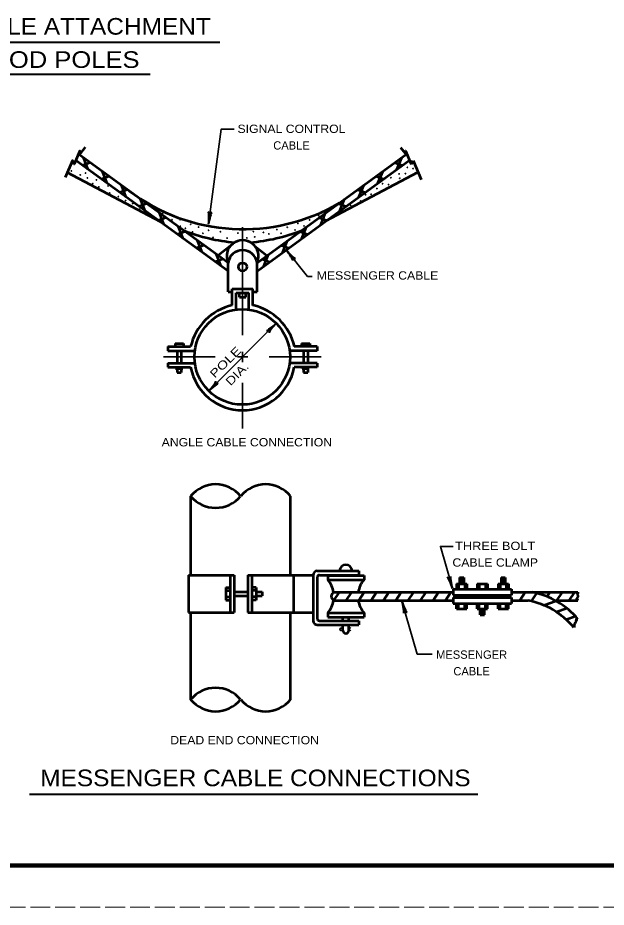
# Model space of a CAD drawing. Extents: x -368 to 312, y -34 to 406.
# Drawn here: x -79.7 to 62, y -34 to 180.1 of the extents above; entities that cross this region are included whole.
import ezdxf
from ezdxf.enums import TextEntityAlignment as Align

# ---------------------------------------------------------------- set-up
doc = ezdxf.new("R2010")
doc.units = 0
doc.header["$LTSCALE"] = 0.8
doc.linetypes.add('LONG_DASHED', pattern=[7.5, 6, -1.5])
doc.layers.add('1', color=7, linetype='Continuous', lineweight=53)
doc.layers.add('61', color=7, linetype='Continuous', lineweight=35)

msp = doc.modelspace()

# ---------------------------------------------------------------- linework, layer by layer
at = {"layer": '1', "lineweight": 40}
for p, q in [((-145.0753, 174.1914), (-31.117, 174.1914)), ((-127.4019, 166.5048), (-47.8685, 166.5048)), ((-76.9022, -6.7668), (31.0441, -6.7668))]:
    msp.add_line(p, q, dxfattribs=at)
at = {"layer": '1'}
for p, q in [((-29.1102, 119.1098), (-65.7546, 145.7335)), ((-29.1103, 121.1099), (-65.1136, 147.2678)), ((-62.7873, 143.5778), (-63.9311, 146.4087)), ((-22.1121, 121.1099), (13.9512, 147.3111)), ((-22.112, 119.1098), (14.5921, 145.7768)), ((11.5652, 143.5778), (12.7089, 146.4087)), ((14.9948, 144.8128), (15.4472, 145.7179)), ((15.4472, 145.7179), (17.386, 141.1555)), ((-62.2976, 145.2218), (-64.0666, 144.5072)), ((11.0754, 145.2218), (12.8444, 144.5072)), ((-45.3876, 130.9361), (-67.8073, 142.8568)), ((-57.7433, 141.913), (-59.5122, 141.1983)), ((-58.2075, 140.2502), (-59.3513, 143.0812)), ((-5.5271, 131.1595), (16.6279, 142.9394)), ((6.5212, 141.913), (8.2901, 141.1983)), ((6.9853, 140.2502), (8.1291, 143.0812)), ((-53.6277, 136.9228), (-54.7713, 139.7537)), ((2.4055, 136.9228), (3.5492, 139.7537)), ((-53.3122, 138.6936), (-55.0812, 137.9788)), ((2.09, 138.6936), (3.859, 137.9788)), ((-48.704, 135.3456), (-50.473, 134.6308)), ((-49.0477, 133.5952), (-50.1913, 136.4262)), ((-2.5182, 135.3456), (-0.7492, 134.6308)), ((-2.1745, 133.5952), (-1.0308, 136.4262)), ((-44.4678, 130.2678), (-45.6116, 133.0987)), ((-6.7543, 130.2678), (-5.6106, 133.0987)), ((-44.0731, 131.981), (-45.8421, 131.2662)), ((-7.1491, 131.981), (-5.3801, 131.2662)), ((-39.4959, 128.6555), (-41.2649, 127.9408)), ((-39.8879, 126.9403), (-41.0317, 129.7713)), ((-11.7263, 128.6555), (-9.9573, 127.9408)), ((-11.3342, 126.9403), (-10.1905, 129.7713)), ((-35.3079, 123.6127), (-36.4517, 126.4437)), ((-15.9142, 123.6127), (-14.7705, 126.4437)), ((-34.9424, 125.3472), (-36.7114, 124.6325)), ((-28.5099, 125.1845), (-31.5014, 122.8473)), ((-22.7444, 125.1845), (-19.7529, 122.8473)), ((-16.2797, 125.3472), (-14.5107, 124.6325)), ((-30.7282, 120.2853), (-31.8719, 123.1163)), ((-20.494, 120.2853), (-19.3502, 123.1163)), ((-30.3417, 122.0046), (-32.1107, 121.2898)), ((-29.112, 114.1098), (-29.112, 121.1098)), ((-22.112, 114.1098), (-22.112, 121.1098)), ((-20.8805, 122.0046), (-19.1115, 121.2898)), ((-29.112, 114.1098), (-28.112, 114.1098)), ((-28.112, 114.8598), (-23.112, 114.8598)), ((-28.112, 110.8598), (-28.112, 114.8598)), ((-27.112, 109.8598), (-27.112, 113.8598)), ((-27.112, 113.8598), (-24.112, 113.8598)), ((-26.362, 112.8598), (-26.362, 113.8598)), ((-24.862, 112.8598), (-24.862, 113.8598)), ((-24.112, 109.8416), (-24.112, 113.8598)), ((-23.112, 110.8416), (-23.112, 114.8598)), ((-23.112, 114.1098), (-22.112, 114.1098)), ((-26.362, 112.8598), (-24.862, 112.8598)), ((-43.612, 100.9345), (-38.112, 100.9345)), ((-43.612, 100.9345), (-43.612, 99.9345)), ((-41.862, 101.6845), (-39.862, 101.6845)), ((-41.862, 101.6845), (-41.862, 100.9345)), ((-39.862, 101.6845), (-39.862, 100.9345)), ((-7.6543, 100.9345), (-13.1543, 100.9345)), ((-11.4136, 101.6682), (-9.4136, 101.6682)), ((-11.4136, 101.6682), (-11.4136, 100.9182)), ((-9.4136, 101.6682), (-9.4136, 100.9182)), ((-7.6543, 100.9345), (-7.6543, 99.9345)), ((-43.612, 99.9345), (-37.0852, 99.9345)), ((-41.362, 99.9345), (-41.362, 96.9345)), ((-40.362, 99.9345), (-40.362, 96.9345)), ((-7.6543, 99.9345), (-14.2778, 99.9345)), ((-10.9136, 99.9182), (-10.9136, 96.9182)), ((-9.9136, 99.9182), (-9.9136, 96.9182)), ((-43.612, 96.9345), (-37.0813, 96.9345)), ((-43.612, 96.9345), (-43.612, 95.9345)), ((-7.6543, 96.9345), (-14.2817, 96.9345)), ((-7.6543, 96.9345), (-7.6543, 95.9345)), ((-43.612, 95.9345), (-38.112, 95.9345)), ((-41.737, 95.6845), (-41.737, 95.9345)), ((-41.737, 95.6845), (-39.987, 95.6845)), ((-41.362, 95.6845), (-41.362, 94.6845)), ((-41.362, 94.6845), (-40.362, 94.6845)), ((-40.362, 95.6845), (-40.362, 94.6845)), ((-39.987, 95.6845), (-39.987, 95.9345)), ((-7.6543, 95.9345), (-13.1543, 95.9345)), ((-11.2886, 95.6682), (-11.2886, 95.9182)), ((-11.2886, 95.6682), (-9.5386, 95.6682)), ((-10.9136, 95.6682), (-10.9136, 94.6682)), ((-10.9136, 94.6682), (-9.9136, 94.6682)), ((-9.9136, 95.6682), (-9.9136, 94.6682)), ((-38.112, 64.9345), (-38.112, 45.9345)), ((-14.112, 64.9345), (-14.112, 45.9345)), ((-38.612, 45.9345), (-38.612, 36.9345)), ((-38.612, 45.9345), (-27.612, 45.9345)), ((-28.612, 45.9345), (-28.612, 36.9345)), ((-27.612, 45.9345), (-27.612, 36.9345)), ((-24.362, 45.9345), (-8.612, 45.9345)), ((-24.362, 45.9345), (-24.362, 36.9345)), ((-23.362, 45.9345), (-23.362, 36.9345)), ((-13.362, 45.9345), (-13.362, 36.9345)), ((-8.612, 45.9345), (-8.612, 34.9345)), ((-7.612, 46.9345), (2.388, 46.9345)), ((-7.612, 45.4345), (-7.612, 35.4345)), ((-7.112, 45.9345), (2.388, 45.9345)), ((-5.112, 45.823), (3.638, 45.823)), ((-5.112, 45.823), (-5.112, 44.823)), ((2.388, 46.9345), (2.388, 45.9345)), ((3.638, 45.823), (3.638, 44.823)), ((26.638, 45.323), (26.638, 43.823)), ((26.638, 45.323), (27.638, 45.323)), ((26.888, 45.073), (27.388, 45.073)), ((27.638, 45.323), (27.638, 43.823)), ((36.6457, 45.323), (36.6457, 43.823)), ((36.6457, 45.323), (37.6457, 45.323)), ((36.8957, 45.073), (37.3957, 45.073)), ((37.6457, 45.323), (37.6457, 43.823)), ((-29.612, 42.9345), (-29.612, 39.9345)), ((-29.612, 42.9345), (-28.612, 42.9345)), ((-22.3722, 42.9345), (-23.3722, 42.9345)), ((-22.3722, 42.9345), (-22.3722, 39.9345)), ((-5.112, 44.823), (3.638, 44.823)), ((25.888, 43.823), (25.888, 42.573)), ((25.888, 43.823), (28.388, 43.823)), ((26.388, 43.823), (26.388, 42.573)), ((26.638, 44.823), (27.638, 44.823)), ((26.638, 44.323), (27.638, 44.323)), ((26.888, 44.573), (27.388, 44.573)), ((26.888, 44.073), (27.388, 44.073)), ((27.888, 43.823), (27.888, 42.573)), ((28.388, 43.823), (28.388, 42.573)), ((30.888, 43.823), (30.888, 42.573)), ((30.888, 43.823), (33.388, 43.823)), ((31.388, 43.823), (31.388, 42.573)), ((32.888, 43.823), (32.888, 42.573)), ((33.388, 43.823), (33.388, 42.573)), ((35.8957, 43.823), (35.8957, 42.573)), ((35.8957, 43.823), (38.3957, 43.823)), ((36.3957, 43.823), (36.3957, 42.573)), ((36.6457, 44.823), (37.6457, 44.823)), ((36.6457, 44.323), (37.6457, 44.323)), ((36.8957, 44.573), (37.3957, 44.573)), ((36.8957, 44.073), (37.3957, 44.073)), ((37.8957, 43.823), (37.8957, 42.573)), ((38.3957, 43.823), (38.3957, 42.573)), ((-29.612, 42.1845), (-28.612, 42.1845)), ((-29.612, 40.6845), (-28.612, 40.6845)), ((-27.612, 41.9345), (-24.362, 41.9345)), ((-27.612, 40.9345), (-24.362, 40.9345)), ((-22.3722, 42.1845), (-23.3722, 42.1845)), ((-22.3722, 40.6845), (-23.3722, 40.6845)), ((-22.3722, 41.9345), (-20.8722, 41.9345)), ((-22.3722, 40.9345), (-20.8722, 40.9345)), ((-20.8722, 41.9345), (-20.8722, 40.9345)), ((-3.612, 39.823), (-2.3077, 41.8266)), ((-3.612, 41.823), (25.138, 41.823)), ((-0.629, 39.823), (0.673, 41.823)), ((2.354, 39.823), (3.656, 41.823)), ((5.3371, 39.823), (6.6391, 41.823)), ((8.3202, 39.823), (9.6222, 41.823)), ((11.3032, 39.823), (12.6052, 41.823)), ((14.2862, 39.823), (15.5882, 41.823)), ((17.2693, 39.823), (18.5713, 41.823)), ((20.2524, 39.823), (21.5544, 41.823)), ((23.2355, 39.823), (24.5375, 41.823)), ((25.138, 42.573), (39.138, 42.573)), ((25.138, 42.573), (25.138, 41.073)), ((25.138, 41.073), (39.138, 41.073)), ((39.138, 42.573), (39.138, 41.073)), ((39.138, 41.823), (55.138, 41.823)), ((41.1338, 39.823), (42.4358, 41.823)), ((43.9972, 39.6389), (45.2574, 41.5748)), ((47.715, 40.7677), (48.402, 41.823)), ((50.083, 39.823), (51.385, 41.823)), ((53.066, 39.823), (54.368, 41.823)), ((-29.612, 39.9345), (-28.612, 39.9345)), ((-22.3722, 39.9345), (-23.3722, 39.9345)), ((-3.612, 39.823), (25.138, 39.823)), ((25.138, 40.573), (39.138, 40.573)), ((25.138, 40.573), (25.138, 39.073)), ((25.138, 39.073), (39.138, 39.073)), ((25.888, 37.8327), (25.888, 39.0827)), ((26.388, 37.8327), (26.388, 39.0827)), ((27.888, 37.8327), (27.888, 39.0827)), ((28.388, 37.8327), (28.388, 39.0827)), ((30.888, 37.8327), (30.888, 39.0827)), ((31.388, 37.8327), (31.388, 39.0827)), ((32.888, 37.8327), (32.888, 39.0827)), ((33.388, 37.8327), (33.388, 39.0827)), ((35.8957, 37.8327), (35.8957, 39.0827)), ((36.3957, 37.8327), (36.3957, 39.0827)), ((37.8957, 37.8327), (37.8957, 39.0827)), ((38.3957, 37.8327), (38.3957, 39.0827)), ((39.138, 40.573), (39.138, 39.073)), ((39.138, 39.823), (43.138, 39.823)), ((46.9516, 38.6697), (49.884, 39.7199)), ((49.699, 39.823), (55.138, 39.823)), ((-38.612, 36.9345), (-27.612, 36.9345)), ((-38.112, 36.9345), (-38.112, 15.9345)), ((-24.362, 36.9345), (-8.612, 36.9345)), ((-14.112, 36.9345), (-14.112, 15.9345)), ((-5.112, 36.823), (3.638, 36.823)), ((-5.112, 36.823), (-5.112, 35.823)), ((3.638, 36.823), (3.638, 35.823)), ((25.888, 37.8327), (28.388, 37.8327)), ((30.888, 37.8327), (33.388, 37.8327)), ((31.638, 36.3327), (31.638, 37.8327)), ((31.638, 37.3327), (32.638, 37.3327)), ((31.638, 36.8327), (32.638, 36.8327)), ((31.888, 37.5827), (32.388, 37.5827)), ((31.888, 37.0827), (32.388, 37.0827)), ((31.888, 36.5827), (32.388, 36.5827)), ((32.638, 36.3327), (32.638, 37.8327)), ((35.8957, 37.8327), (38.3957, 37.8327)), ((49.9327, 37.0819), (52.4453, 37.9817)), ((-7.112, 34.9345), (2.388, 34.9345)), ((-5.112, 35.823), (3.638, 35.823)), ((-1.487, 34.9345), (-1.487, 35.823)), ((0.013, 34.9345), (0.013, 35.823)), ((2.388, 34.9345), (2.388, 33.9345)), ((31.638, 36.3327), (32.638, 36.3327)), ((52.2806, 35.2673), (54.495, 36.0604)), ((-7.612, 33.9345), (2.388, 33.9345)), ((-1.487, 32.573), (-1.487, 33.9345)), ((0.013, 32.573), (0.013, 33.9345))]:
    msp.add_line(p, q, dxfattribs=at)
at = {"layer": '1', "lineweight": 35}
for p, q in [((-25.612, 103.6845), (-25.612, 129.6845)), ((-33.771, 90.2755), (-17.5078, 106.5387)), ((-25.612, 97.1845), (-25.612, 99.6845)), ((-44.612, 98.4345), (-32.1815, 98.4345)), ((-26.862, 98.4345), (-24.362, 98.4345)), ((-19.1815, 98.4345), (-6.6543, 98.4345)), ((-25.612, 92.1845), (-25.612, 81.1845)), ((0.0604, 32.8882), (0.4582, 33.286)), ((0.0604, 32.8882), (0.4582, 32.4904))]:
    msp.add_line(p, q, dxfattribs=at)
for points in [[(-33.8061, 130.4243), (-30.7755, 153.222), (-27.6525, 153.2488)], [(-15.0168, 124.1321), (-9.9758, 117.7928), (-8.8524, 117.8217)], [(24.8981, 42.7465), (22.0152, 52.8131), (25.0829, 52.8131)], [(12.7677, 39.6449), (16.4668, 26.9121), (20.0113, 26.9121)]]:
    msp.add_lwpolyline(points, dxfattribs=at)
at = {"layer": '1'}
for points in [[(-63.5314, 148.9304), (-64.669, 147.4956), (-64.7821, 148.0613), (-66.1392, 144.8128), (-66.5915, 145.7179), (-68.3361, 141.6127)], [(12.4505, 148.8504), (13.5247, 147.4956), (13.6377, 148.0613), (14.9948, 144.8128)], [(55.138, 41.823), (55.1493, 41.6619), (55.0187, 41.4007), (54.9861, 41.2373), (55.084, 41.0087), (55.1493, 40.8128), (55.1167, 40.6821), (54.9534, 40.4535), (54.8228, 40.2575), (54.9534, 40.1269), (55.0513, 39.9309), (55.138, 39.823)], [(55.138, 35.323), (54.7248, 35.2932), (54.8555, 35.1626), (54.8228, 35.0646), (54.6596, 34.9012), (54.6596, 34.7053), (54.6269, 34.6727), (54.4637, 34.4441), (54.3983, 34.2807), (54.3004, 34.1827), (54.2351, 33.8888), (54.2351, 33.4969), (54.138, 33.323)]]:
    msp.add_lwpolyline(points, dxfattribs=at)
at = {"layer": '1', "lineweight": 35}
for centre in [(14.1015, 144.0448), (15.4342, 143.7567), (-66.8391, 143.1857), (-64.7054, 142.2567), (-63.4001, 142.6836), (-62.9733, 141.5033), (10.1035, 141.5588), (12.0845, 142.4956), (12.2286, 141.4507), (13.5972, 142.5677), (-61.6931, 140.1474), (-60.7894, 141.0513), (-60.187, 139.3438), (-57.978, 139.595), (8.1225, 140.1177), (9.5633, 139.9015), (-57.5763, 137.9126), (-55.4928, 137.0086), (4.0165, 137.4515), (5.3492, 137.5956), (6.7538, 138.9648), (-53.7859, 136.0795), (-52.0538, 135.3513), (0.4148, 134.9294), (2.8639, 135.9742), (-50.3971, 133.9702), (-49.1922, 133.242), (-45.9791, 133.7693), (-44.7993, 133.0662), (-5.6183, 133.4342), (-1.5302, 133.5963), (-42.5652, 131.4592), (-40.6285, 131.4592), (-12.2996, 130.5698), (-9.4722, 131.4165), (-7.2571, 132.4073), (-40.5639, 129.8771), (-39.3697, 129.3928), (-38.0786, 130.3614), (-37.6267, 128.521), (-36.2065, 129.6833), (-33.7857, 128.9084), (-30.9452, 128.5532), (-23.005, 128.5856), (-20.5843, 128.3918), (-17.3565, 129.0699), (-14.8388, 129.6511), (-12.9479, 129.0025), (-10.7868, 129.9573), (-35.1736, 128.1981), (-32.7205, 127.1972), (-29.3314, 127.0357), (-26.7169, 128.2304), (-24.5543, 127.068), (-22.6822, 127.3263), (-19.2608, 128.0367), (-16.3559, 128.1981)]:
    msp.add_circle(centre, 0.0565, dxfattribs=at)
at = {"layer": '1'}
for centre, radius in [((-25.6042, 120.1021), 1), ((-25.6815, 98.4492), 11.5)]:
    msp.add_circle(centre, radius, dxfattribs=at)
for centre, radius, start, end in [((-25.4453, 174.7196), 45.5354, 232.79972, 300.56324), ((-23.8416, 169.8697), 44.0119, 248.83745, 265.22991), ((-27.4079, 169.8697), 44.0119, 274.79911, 291.24419), ((-25.612, 122.6745), 3.8338, 335.91356, 204.08644), ((-25.612, 120.5682), 3.5417, 8.79741, 171.20259), ((-25.2213, 97.9471), 13.2323, 102.61843, 166.95216), ((-25.991, 97.9471), 13.2323, 13.04784, 77.38157), ((-25.6332, 98.3128), 12.7035, 190.79056, 349.20944), ((-32.112, 60.0278), 7.7508, 39.27573, 140.72427), ((-20.0563, 60.0278), 7.7508, 39.27573, 140.72427), ((-32.112, 69.8642), 7.7508, 219.27573, 320.72427), ((-0.737, 46.9102), 1.5002, 0.92934, 179.07066), ((-7.612, 45.9345), 1, 90, 180), ((-7.112, 45.4345), 0.5, 90, 180), ((-9.6953, 40.823), 6.0833, 9.07313, 41.11209), ((8.234, 40.823), 6.0833, 138.88791, 170.53858), ((-3.1264, 40.823), 1.1117, 115.90299, 244.09701), ((40.6217, 23.3147), 18.8394, 39.59864, 79.2429), ((-9.6953, 40.823), 6.0833, 318.88791, 350.92687), ((8.234, 40.823), 6.0833, 189.46143, 221.11209), ((39.6217, 21.3147), 18.8394, 39.59864, 79.2429), ((-7.612, 34.9345), 1, 180, 270), ((-7.112, 35.4345), 0.5, 180, 270), ((-0.737, 32.6558), 0.7546, 186.30051, 353.69949), ((-32.112, 11.0455), 7.7508, 39.27573, 140.72427), ((-32.112, 20.8819), 7.7508, 219.27573, 320.72427), ((-20.0563, 20.8819), 7.7508, 219.27573, 320.72427)]:
    msp.add_arc(centre, radius, start, end, dxfattribs=at)
at = {"layer": '1', "lineweight": 35}
for centre, radius, start, end in [((-1.8826, 32.8877), 0.3001, 75.19279, 284.80721), ((-1.969, 33.0931), 0.5217, 288.22327, 331.26209), ((-1.9715, 32.6793), 0.5253, 28.89529, 71.61936)]:
    msp.add_arc(centre, radius, start, end, dxfattribs=at)
at = {"layer": '1', "lineweight": 40}
for centre, major_axis, ratio, start_param, end_param in [((-33.9362, 131.5423), (-0.0805, -1.7907), 0.122415, 0.89635335, 3.14159265), ((-33.4487, 131.5071), (-0.4056, -1.718), 0.07063, 3.14071475, 5.41810995), ((-14.485, 123.1234), (-0.9557, 1.4841), 0.07063, 3.14071475, 5.41810995), ((-14.1213, 123.45), (-1.2336, 1.3005), 0.122415, 0.89635335, 3.14159265), ((-18.4498, 105.896), (-1.3662, -1.1178), 0.07063, 6.28230741, 8.55970261), ((-18.4498, 105.896), (-1.3662, -1.1178), 0.07063, 6.28230741, 8.55970261), ((-18.0841, 105.5717), (1.1523, 1.3731), 0.122415, 0.89635335, 3.14159265), ((-18.0841, 105.5717), (1.1523, 1.3731), 0.122415, 0.89635335, 3.14159265), ((-33.1948, 91.2425), (-1.1523, -1.3731), 0.122415, 0.89635335, 3.14159265), ((-32.8291, 90.9182), (1.3662, 1.1178), 0.07063, 6.28230741, 8.55970261), ((24.332, 43.7195), (0.6417, -1.6737), 0.122415, 0.89635335, 3.14159265), ((24.332, 43.7195), (0.6417, -1.6737), 0.122415, 0.89635335, 3.14159265), ((24.793, 43.882), (-0.3147, 1.7369), 0.07063, 6.28230741, 8.55970261), ((24.793, 43.882), (-0.3147, 1.7369), 0.07063, 6.28230741, 8.55970261), ((12.8771, 38.5099), (0.3213, -1.7357), 0.07063, 6.28230741, 8.55970261), ((13.3375, 38.6741), (-0.6481, 1.6712), 0.122415, 0.89635335, 3.14159265)]:
    msp.add_ellipse(centre, major_axis=major_axis, ratio=ratio, start_param=start_param, end_param=end_param, dxfattribs=at)
at = {"layer": '61', "lineweight": 158}
msp.add_line((301.1585, -24.0008), (-337.9015, -23.9808), dxfattribs=at)
at = {"layer": '61', "linetype": 'LONG_DASHED', "lineweight": 13}
msp.add_line((312.0985, -33.9808), (-367.9615, -34.0007), dxfattribs=at)

# ---------------------------------------------------------------- texts
at = {"layer": '1'}
for s, height, width, p in [('INTERCONNECT CABLE ATTACHMENT', 4, 1.1, (-88.0212, 175.9992)), ('METAL OR WOOD POLES', 4, 1.15, (-88.0211, 167.9992)), ('SIGNAL CONTROL', 2, 1.1, (-13.8305, 152.3394)), ('MESSENGER CABLE', 2, 1.1, (6.88, 117.046)), ('ANGLE CABLE CONNECTION', 2, 1.1, (-24.5735, 76.9047)), ('THREE BOLT', 2, 1.15, (35.223, 51.9609)), ('CABLE CLAMP', 2, 1.1, (35.223, 47.9609)), ('DEAD END CONNECTION', 2, 1.1, (-25.1161, 5.21)), ('MESSENGER CABLE CONNECTIONS', 4, 1.1, (-22.5236, -4.8791))]:
    msp.add_text(s, height=height, dxfattribs=dict(at, width=width)).set_placement(p, align=Align.CENTER)
for s, p in [('CABLE', (-13.8304, 148.3394)), ('MESSENGER', (29.5386, 25.792)), ('CABLE', (29.5386, 21.792))]:
    msp.add_text(s, height=2, dxfattribs=at).set_placement(p, align=Align.CENTER)
for s, width, p in [('POLE', 1.3, (-29.0258, 96.4684)), ('DIA.', 1.25, (-26.1974, 93.6399))]:
    msp.add_text(s, height=2, rotation=45, dxfattribs=dict(at, width=width)).set_placement(p, align=Align.CENTER)

doc.saveas('drawing.dxf')
